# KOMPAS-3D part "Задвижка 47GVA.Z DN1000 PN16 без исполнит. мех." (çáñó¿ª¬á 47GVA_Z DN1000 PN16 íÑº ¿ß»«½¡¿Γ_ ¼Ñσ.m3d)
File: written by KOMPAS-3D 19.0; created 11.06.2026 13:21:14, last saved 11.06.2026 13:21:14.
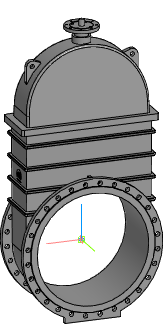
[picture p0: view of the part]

Document properties: Автор: Евгений; Полное имя файла: Z:\3.Личные\kachalov\001_3d для проектировщиков\2.2 Тип 47GVA, 47GVA.Z\_stp\_stp_Задвижка 47GVA.Z DN350-DN1200 без исп.мех\Задвижка 47GVA_Z DN1000 PN16 без исполнит_ мех.m3d

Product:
- Part/product: Задвижка 47GVA.Z DN1000 PN16 без исполнит. мех.

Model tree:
1. Операция без истории:1  (labels: Задвижка 47GVA.Z DN1000 PN16 без исполнит. мех.)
